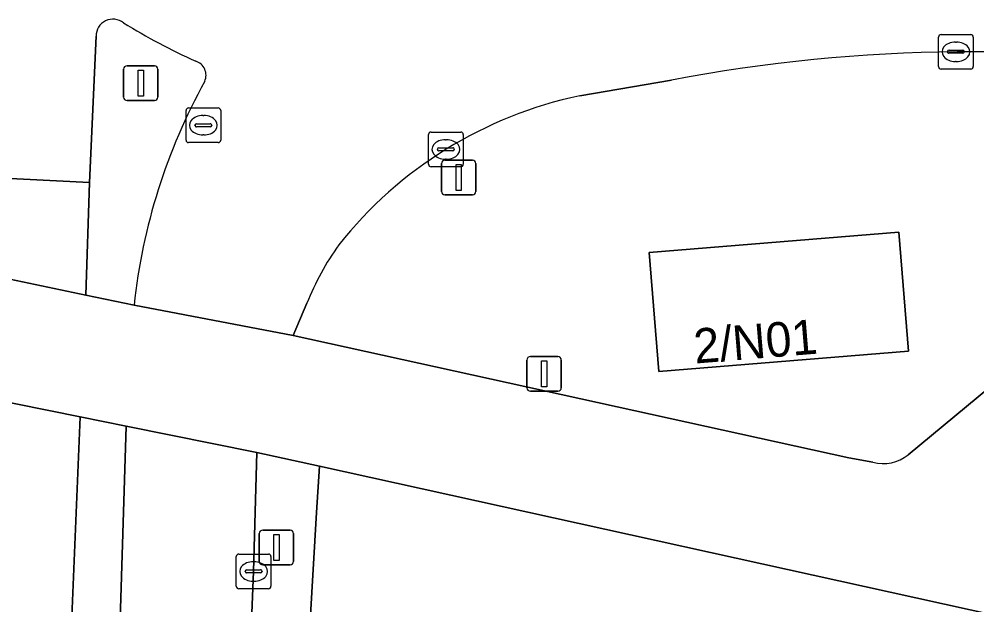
# Model space of a CAD drawing. Extents: x 161090 to 161692, y 379509 to 380907.
# Drawn here: x 161453.8 to 161481.41, y 379792.93 to 379809.82 of the extents above; entities that cross this region are included whole.
import ezdxf

# ---------------------------------------------------------------- set-up
doc = ezdxf.new("R2010")
doc.units = 0
for name, color, linetype in [('IMGEO_Fietspad_gesloten', 7, 'Continuous'), ('IMGEO_Groenvoorziening', 7, 'Continuous'), ('IMGEO_Kolk', 7, 'Continuous'), ('IMGEO_Lichtmast', 7, 'Continuous'), ('IMGEO_Pand', 7, 'Continuous'), ('IMGEO_Pand_nummerreeks', 7, 'Continuous'), ('IMGEO_Rijbaan_lokaal_gesloten', 7, 'Continuous'), ('IMGEO_Rijbaan_lokaal_open', 7, 'Continuous'), ('IMGEO_Rioolput', 7, 'Continuous'), ('IMGEO_Verkeerseiland_open', 7, 'Continuous'), ('IMGEO_Verkeersregelinstallatiepaal', 7, 'Continuous')]:
    doc.layers.add(name, color=color, linetype=linetype)

msp = doc.modelspace()

# ---------------------------------------------------------------- linework, layer by layer
at = {"layer": 'IMGEO_Fietspad_gesloten'}
for points in [[(161478.409, 379797.042), (161477.716, 379797.168), (161461.697, 379800.699), (161457.114, 379801.568), (161455.727, 379801.86), (161451.884, 379802.669), (161449.906, 379803.09), (161446.705, 379803.667)], [(161482.792, 379800.046), (161479.425, 379797.257)], [(161449.796, 379799.515), (161449.821, 379799.51), (161451.795, 379799.111), (161455.565, 379798.35), (161456.891, 379798.083), (161460.655, 379797.323), (161462.462, 379796.924), (161483.43, 379792.296), (161487.83, 379791.325), (161496.812, 379789.457), (161497.951, 379789.22), (161500.096, 379788.774), (161506.898, 379787.36), (161515.765, 379785.516)]]:
    msp.add_lwpolyline(points, dxfattribs=at)
msp.add_arc((161478.707, 379798.14), 1.138, 254.7976, 309.0991, dxfattribs=at)
at = {"layer": 'IMGEO_Groenvoorziening'}
for points in [[(161472.604, 379808.056), (161469.963, 379807.607)], [(161462.098, 379801.624), (161461.697, 379800.699), (161477.716, 379797.168), (161478.409, 379797.042)], [(161479.425, 379797.257), (161482.792, 379800.046)], [(161461.725, 379784.582), (161462.191, 379792.466), (161462.375, 379795.591), (161462.462, 379796.924), (161460.655, 379797.323), (161460.562, 379793.893), (161460.175, 379784.242), (161459.479, 379767.451)], [(161483.841, 379746.81), (161488.001, 379750.501), (161489.356, 379780.841), (161497.951, 379789.22), (161496.812, 379789.457), (161487.83, 379791.325), (161483.43, 379792.296), (161462.462, 379796.924), (161462.375, 379795.591), (161462.191, 379792.466), (161483.335, 379790.687), (161488.266, 379790.227), (161486.745, 379756.255), (161481.667, 379756.674), (161480.85, 379756.742)]]:
    msp.add_lwpolyline(points, dxfattribs=at)
msp.add_lwpolyline([(161479.158, 379803.678), (161479.44, 379800.246), (161472.241, 379799.654), (161471.959, 379803.086)], close=True, dxfattribs=at)
for centre, radius, start, end in [((161481.255, 379762.958), 45.92, 80.177, 100.8587), ((161472.434, 379795.849), 12.014, 101.8694, 141.6195), ((161469.541, 379798.661), 8.011, 144.5398, 158.2964), ((161478.707, 379798.14), 1.138, 254.7976, 309.0991)]:
    msp.add_arc(centre, radius, start, end, dxfattribs=at)
at = {"layer": 'IMGEO_Kolk'}
for p, q in [((161480.303, 379808.45), (161480.303, 379809.302)), ((161480.378, 379809.376), (161481.23, 379809.376)), ((161481.304, 379809.302), (161481.304, 379808.45)), ((161480.791, 379809.156), (161480.816, 379809.156)), ((161480.562, 379808.87), (161480.562, 379808.882)), ((161481, 379808.833), (161480.602, 379808.833)), ((161480.605, 379808.919), (161481.003, 379808.919)), ((161481.046, 379808.882), (161481.046, 379808.87)), ((161480.814, 379808.596), (161480.789, 379808.596)), ((161481.23, 379808.376), (161480.378, 379808.376)), ((161465.678, 379806.561), (161466.53, 379806.561)), ((161465.603, 379805.635), (161465.603, 379806.487)), ((161466.091, 379806.341), (161466.116, 379806.341)), ((161466.604, 379806.487), (161466.604, 379805.635)), ((161465.862, 379806.055), (161465.862, 379806.067)), ((161466.3, 379806.018), (161465.902, 379806.018)), ((161465.905, 379806.104), (161466.303, 379806.104)), ((161466.346, 379806.067), (161466.346, 379806.055)), ((161466.114, 379805.781), (161466.089, 379805.781)), ((161466.53, 379805.561), (161465.678, 379805.561)), ((161460.136, 379794.393), (161460.988, 379794.393)), ((161460.061, 379793.467), (161460.061, 379794.319)), ((161460.549, 379794.173), (161460.574, 379794.173)), ((161461.062, 379794.319), (161461.062, 379793.467)), ((161460.32, 379793.887), (161460.32, 379793.899)), ((161460.758, 379793.85), (161460.36, 379793.85)), ((161460.363, 379793.936), (161460.761, 379793.936)), ((161460.804, 379793.899), (161460.804, 379793.887)), ((161460.572, 379793.613), (161460.547, 379793.613)), ((161460.988, 379793.393), (161460.136, 379793.393))]:
    msp.add_line(p, q, dxfattribs=at)
for points in [[(161480.303, 379808.45), (161480.303, 379809.302)], [(161480.378, 379809.376), (161481.23, 379809.376)], [(161481.304, 379809.302), (161481.304, 379808.45)], [(161481.23, 379808.376), (161480.378, 379808.376)], [(161465.678, 379806.561), (161466.53, 379806.561)], [(161465.603, 379805.635), (161465.603, 379806.487)], [(161466.604, 379806.487), (161466.604, 379805.635)], [(161466.53, 379805.561), (161465.678, 379805.561)], [(161460.136, 379794.393), (161460.988, 379794.393)], [(161460.061, 379793.467), (161460.061, 379794.319)], [(161461.062, 379794.319), (161461.062, 379793.467)], [(161460.988, 379793.393), (161460.136, 379793.393)]]:
    msp.add_lwpolyline(points, dxfattribs=at)
for centre, radius, start, end in [((161480.38, 379809.3), 0.0765, 91.552, 178.448), ((161480.38, 379809.3), 0.0765, 91.552, 178.448), ((161481.228, 379809.3), 0.0765, 1.552, 88.448), ((161481.228, 379809.3), 0.0765, 1.552, 88.448), ((161480.602, 379808.879), 0.0403, 85.8775, 175.7526), ((161480.599, 379808.869), 0.0366, 178.938, 274.7102), ((161481.003, 379808.876), 0.043, 264.8664, 352.4533), ((161481.007, 379808.881), 0.0386, 1.7309, 96.639), ((161480.38, 379808.452), 0.0765, 181.552, 268.448), ((161480.38, 379808.452), 0.0765, 181.552, 268.448), ((161481.228, 379808.452), 0.0765, 271.552, 358.448), ((161481.228, 379808.452), 0.0765, 271.552, 358.448), ((161465.68, 379806.485), 0.0765, 91.552, 178.448), ((161465.68, 379806.485), 0.0765, 91.552, 178.448), ((161466.528, 379806.485), 0.0765, 1.552, 88.448), ((161466.528, 379806.485), 0.0765, 1.552, 88.448), ((161465.902, 379806.064), 0.0403, 85.8775, 175.7526), ((161465.899, 379806.054), 0.0366, 178.938, 274.7102), ((161466.303, 379806.061), 0.043, 264.8664, 352.4533), ((161466.307, 379806.066), 0.0386, 1.7309, 96.639), ((161465.68, 379805.637), 0.0765, 181.552, 268.448), ((161465.68, 379805.637), 0.0765, 181.552, 268.448), ((161466.528, 379805.637), 0.0765, 271.552, 358.448), ((161466.528, 379805.637), 0.0765, 271.552, 358.448), ((161460.138, 379794.317), 0.0765, 91.552, 178.448), ((161460.138, 379794.317), 0.0765, 91.552, 178.448), ((161460.986, 379794.317), 0.0765, 1.552, 88.448), ((161460.986, 379794.317), 0.0765, 1.552, 88.448), ((161460.36, 379793.896), 0.0403, 85.8775, 175.7526), ((161460.357, 379793.886), 0.0366, 178.938, 274.7102), ((161460.761, 379793.893), 0.043, 264.8664, 352.4533), ((161460.765, 379793.898), 0.0386, 1.7309, 96.639), ((161460.138, 379793.469), 0.0765, 181.552, 268.448), ((161460.138, 379793.469), 0.0765, 181.552, 268.448), ((161460.986, 379793.469), 0.0765, 271.552, 358.448), ((161460.986, 379793.469), 0.0765, 271.552, 358.448)]:
    msp.add_arc(centre, radius, start, end, dxfattribs=at)
for centre, major_axis, ratio, start_param, end_param in [((161480.79, 379808.876), (-0.387, 0.002), 0.722429, 4.712389, 7.853982), ((161480.815, 379808.876), (-0.39, 0.002), 0.717154, 1.570796, 4.712389), ((161466.09, 379806.061), (-0.387, 0.002), 0.722429, 4.712389, 7.853982), ((161466.115, 379806.061), (-0.39, 0.002), 0.717154, 1.570796, 4.712389), ((161460.548, 379793.893), (-0.387, 0.002), 0.722429, 4.712389, 7.853982), ((161460.573, 379793.893), (-0.39, 0.002), 0.717154, 1.570796, 4.712389)]:
    msp.add_ellipse(centre, major_axis=major_axis, ratio=ratio, start_param=start_param, end_param=end_param, dxfattribs=at)
at = {"layer": 'IMGEO_Lichtmast'}
for p, q in [((161456.913, 379808.472), (161457.703, 379808.472)), ((161457.703, 379808.472), (161456.913, 379808.472)), ((161456.813, 379807.572), (161456.813, 379808.372)), ((161456.813, 379808.372), (161456.813, 379807.572)), ((161457.803, 379808.372), (161457.803, 379807.572)), ((161457.803, 379807.572), (161457.803, 379808.372)), ((161457.703, 379807.472), (161456.913, 379807.472)), ((161456.913, 379807.472), (161457.703, 379807.472)), ((161468.44, 379799.188), (161468.44, 379799.988)), ((161468.44, 379799.988), (161468.44, 379799.188)), ((161468.54, 379800.088), (161469.33, 379800.088)), ((161469.33, 379800.088), (161468.54, 379800.088)), ((161469.43, 379799.988), (161469.43, 379799.188)), ((161469.43, 379799.188), (161469.43, 379799.988)), ((161469.33, 379799.088), (161468.54, 379799.088)), ((161468.54, 379799.088), (161469.33, 379799.088)), ((161460.724, 379794.184), (161460.724, 379794.984)), ((161460.724, 379794.984), (161460.724, 379794.184)), ((161460.824, 379795.084), (161461.614, 379795.084)), ((161461.614, 379795.084), (161460.824, 379795.084)), ((161461.714, 379794.984), (161461.714, 379794.184)), ((161461.714, 379794.184), (161461.714, 379794.984)), ((161461.614, 379794.084), (161460.824, 379794.084)), ((161460.824, 379794.084), (161461.614, 379794.084))]:
    msp.add_line(p, q, dxfattribs=at)
for points in [[(161457.233, 379808.347), (161457.383, 379808.347), (161457.383, 379807.597), (161457.233, 379807.597), (161457.233, 379808.347)], [(161468.86, 379799.963), (161469.01, 379799.963), (161469.01, 379799.213), (161468.86, 379799.213), (161468.86, 379799.963)], [(161461.144, 379794.959), (161461.294, 379794.959), (161461.294, 379794.209), (161461.144, 379794.209), (161461.144, 379794.959)]]:
    msp.add_lwpolyline(points, dxfattribs=at)
for centre, start, end in [((161456.913, 379808.372), 90, 180), ((161456.913, 379808.372), 90, 180), ((161457.703, 379808.372), 0, 90), ((161457.703, 379808.372), 360, 90), ((161456.913, 379807.572), 180, 270), ((161456.913, 379807.572), 180, 270), ((161457.703, 379807.572), 270, 0), ((161457.703, 379807.572), 270, 0), ((161468.54, 379799.988), 90, 180), ((161468.54, 379799.988), 90, 180), ((161469.33, 379799.988), 0, 90), ((161469.33, 379799.988), 360, 90), ((161468.54, 379799.188), 180, 270), ((161468.54, 379799.188), 180, 270), ((161469.33, 379799.188), 270, 0), ((161469.33, 379799.188), 270, 0), ((161460.824, 379794.984), 90, 180), ((161460.824, 379794.984), 90, 180), ((161461.614, 379794.984), 0, 90), ((161461.614, 379794.984), 360, 90), ((161460.824, 379794.184), 180, 270), ((161460.824, 379794.184), 180, 270), ((161461.614, 379794.184), 270, 0), ((161461.614, 379794.184), 270, 0)]:
    msp.add_arc(centre, 0.1, start, end, dxfattribs=at)
at = {"layer": 'IMGEO_Pand'}
msp.add_lwpolyline([(161472.241, 379799.654), (161479.44, 379800.246), (161479.158, 379803.678), (161471.959, 379803.086)], close=True, dxfattribs=at)
at = {"layer": 'IMGEO_Rijbaan_lokaal_gesloten'}
for points in [[(161452.099, 379807.387), (161452.033, 379805.542), (161452.02, 379805.298), (161455.836, 379805.108), (161456.019, 379809.326)], [(161469.963, 379807.607), (161472.604, 379808.056)], [(161457.114, 379801.568), (161461.697, 379800.699), (161462.098, 379801.624)]]:
    msp.add_lwpolyline(points, dxfattribs=at)
msp.add_lwpolyline([(161455.836, 379805.108), (161452.02, 379805.298), (161451.884, 379802.669), (161455.727, 379801.86)], close=True, dxfattribs=at)
for centre, radius, start, end in [((161456.509, 379809.328), 0.49, 51.2716, 180.2349), ((161466.524, 379825.439), 18.484, 238.3153, 245.6142), ((161481.255, 379762.958), 45.92, 80.177, 100.8587), ((161458.768, 379808.201), 0.422, 335.4898, 72.9492), ((161474.202, 379799.726), 17.187, 151.1231, 173.8478), ((161472.434, 379795.849), 12.014, 101.8694, 141.6195), ((161469.541, 379798.661), 8.011, 144.5398, 158.2964)]:
    msp.add_arc(centre, radius, start, end, dxfattribs=at)
at = {"layer": 'IMGEO_Rijbaan_lokaal_open'}
for points in [[(161455.074, 379786.688), (161455.243, 379790.742), (161455.565, 379798.35), (161451.795, 379799.111), (161451.452, 379790.786), (161451.401, 379789.546), (161451.383, 379789.129), (161451.198, 379784.62), (161460.175, 379784.242), (161460.562, 379793.893), (161460.655, 379797.323)], [(161460.655, 379797.323), (161456.891, 379798.083), (161456.655, 379790.65), (161456.461, 379786.641)]]:
    msp.add_lwpolyline(points, dxfattribs=at)
at = {"layer": 'IMGEO_Rioolput'}
for p, q in [((161458.613, 379806.332), (161458.613, 379807.184)), ((161458.688, 379807.258), (161459.54, 379807.258)), ((161459.614, 379807.184), (161459.614, 379806.332)), ((161458.915, 379806.801), (161459.313, 379806.801)), ((161459.101, 379807.038), (161459.126, 379807.038)), ((161458.872, 379806.752), (161458.872, 379806.764)), ((161459.31, 379806.715), (161458.912, 379806.715)), ((161459.356, 379806.764), (161459.356, 379806.752)), ((161459.54, 379806.258), (161458.688, 379806.258)), ((161459.124, 379806.478), (161459.099, 379806.478))]:
    msp.add_line(p, q, dxfattribs=at)
for points in [[(161458.613, 379806.332), (161458.613, 379807.184)], [(161458.688, 379807.258), (161459.54, 379807.258)], [(161459.614, 379807.184), (161459.614, 379806.332)], [(161459.54, 379806.258), (161458.688, 379806.258)]]:
    msp.add_lwpolyline(points, dxfattribs=at)
for centre, radius, start, end in [((161458.69, 379807.182), 0.0765, 91.552, 178.448), ((161458.69, 379807.182), 0.0765, 91.552, 178.448), ((161459.538, 379807.182), 0.0765, 1.552, 88.448), ((161459.538, 379807.182), 0.0765, 1.552, 88.448), ((161458.912, 379806.761), 0.0403, 85.8775, 175.7526), ((161459.317, 379806.763), 0.0386, 1.7309, 96.639), ((161458.909, 379806.751), 0.0366, 178.938, 274.7102), ((161459.313, 379806.758), 0.043, 264.8664, 352.4533), ((161458.69, 379806.334), 0.0765, 181.552, 268.448), ((161458.69, 379806.334), 0.0765, 181.552, 268.448), ((161459.538, 379806.334), 0.0765, 271.552, 358.448), ((161459.538, 379806.334), 0.0765, 271.552, 358.448)]:
    msp.add_arc(centre, radius, start, end, dxfattribs=at)
for centre, major_axis, ratio, start_param, end_param in [((161459.1, 379806.758), (-0.387, 0.002), 0.722429, 4.712389, 7.853982), ((161459.125, 379806.758), (-0.39, 0.002), 0.717154, 1.570796, 4.712389)]:
    msp.add_ellipse(centre, major_axis=major_axis, ratio=ratio, start_param=start_param, end_param=end_param, dxfattribs=at)
at = {"layer": 'IMGEO_Verkeerseiland_open'}
for points in [[(161456.019, 379809.326), (161455.836, 379805.108), (161455.727, 379801.86), (161457.114, 379801.568)], [(161456.891, 379798.083), (161455.565, 379798.35), (161455.243, 379790.742), (161455.074, 379786.688)], [(161456.461, 379786.641), (161456.655, 379790.65), (161456.891, 379798.083)]]:
    msp.add_lwpolyline(points, dxfattribs=at)
for centre, radius, start, end in [((161456.509, 379809.328), 0.49, 51.2716, 180.2349), ((161466.524, 379825.439), 18.484, 238.3153, 245.6142), ((161458.768, 379808.201), 0.422, 335.4898, 72.9492), ((161474.202, 379799.726), 17.187, 151.1231, 173.8478)]:
    msp.add_arc(centre, radius, start, end, dxfattribs=at)
at = {"layer": 'IMGEO_Verkeersregelinstallatiepaal'}
for p, q in [((161466.077, 379805.751), (161466.867, 379805.751)), ((161466.867, 379805.751), (161466.077, 379805.751)), ((161465.977, 379804.851), (161465.977, 379805.651)), ((161465.977, 379805.651), (161465.977, 379804.851)), ((161466.967, 379805.651), (161466.967, 379804.851)), ((161466.967, 379804.851), (161466.967, 379805.651)), ((161466.867, 379804.751), (161466.077, 379804.751)), ((161466.077, 379804.751), (161466.867, 379804.751))]:
    msp.add_line(p, q, dxfattribs=at)
msp.add_lwpolyline([(161466.397, 379805.626), (161466.547, 379805.626), (161466.547, 379804.876), (161466.397, 379804.876), (161466.397, 379805.626)], dxfattribs=at)
for centre, start, end in [((161466.077, 379805.651), 90, 180), ((161466.077, 379805.651), 90, 180), ((161466.867, 379805.651), 0, 90), ((161466.867, 379805.651), 360, 90), ((161466.077, 379804.851), 180, 270), ((161466.077, 379804.851), 180, 270), ((161466.867, 379804.851), 270, 0), ((161466.867, 379804.851), 270, 0)]:
    msp.add_arc(centre, 0.1, start, end, dxfattribs=at)

# ---------------------------------------------------------------- texts
at = {"layer": 'IMGEO_Pand_nummerreeks'}
msp.add_text('2/N01', height=1, rotation=4.6583, dxfattribs=at).set_placement((161473.287, 379799.886))

doc.saveas('drawing.dxf')
